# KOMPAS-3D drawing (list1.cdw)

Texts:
  ТОТС.ОПП.00.000.Д1
  График загрузки мастерской. График потребности рабочих по специально- стям. Пространственная организация рабочего места.
  Текст на чертеже
  Размерные надписи
  Шероховатость
  Линия-выноска #1
  Линия-выноска #2
  Линия-выноска #3
  Отклонения формы и база
  Заголовок таблицы
  Ячейка таблицы
  Стрелка вида
  Обозначение изменения
  Фигурная скобка
  Номер узла
  Марка координационной оси
  VRCB
  Выносная надпись
  Обозначение узла
  Марка/позиционное обозначение с линией-выноской
  Марка/позиционное обозначение на линии
  Марка/позиционное обозначение без линии-выноски
  Лист
  Листов
  Рабочее место
  Участок
  Механический
  Пространственная организация
  рабочего места
  (схема)
  Оборудование, оргоснастка, инструмент
  Кол-во
  ГОСТ, ТУ, тип
  модель
  Технологическое
  Станок круглошлифовальный
  Оргоснастка
  Подставка - решетка
  Стол приемный передвижной
  Тумбочка
  Стул подъемно - поворотный
  Урна для мусора
  Техоснастка
  Круг шлифовальный
  Приспособление для правки
  шлифовального круга с кругом
  из карбида кремния ВТ-4Т
  Центр вращающийся
  Морзе №4
  Инструмент
  Ключи гаечные двухсторонние:
  8-10,12-14,17-19,22-24 мм
  ГОСТ 2839-71
  Молоток слесарный
  ПИМ 7215-54
  Напильник плоский личный
  ГОСТ 1465-69
  Напильник полукруглый личный
  Образцы шероховатости
  поверхности
  ГОСТ 9378-60
  Микрометр гладкий
  ГОСТ 6507-60
  Нутромер микрометрический
  ГОСТ 10-58
  Штангенциркуль с двухсто-
  ронним расположением губок
  для наружных и внутренних
  измерений 0-125 мм
  ГОСТ 9378-75
  Инвентарь
  Щетка капроновая
  Документация
  Инструкция по технике безо-
  пасности
  Карта организации труда
  Маршрутный лист
  Технологические карты на
  восстановление и изготов-
  ление деталей
  по 1
  Ящик для хранения мелкой техоснастки
  Ящик для хранения крупной техоснастки
  Ящик для хранения инвентаря
  ГОСТ 2424-67
  Ящик для слесарного и вспомогательного
  инструмента
  Ящик для хранения приспособлений
  Ящик для хранения мерительного инструмента
  Ящик для хранения документации
  ОРГ 9033.000 ЦКТБ
  Россельхозтехника
  ГОСТ 6565-67
  ГОСТ 4785-64
  Обтирочный материал
  Направление
  грузопотока
  янв   фев  март   апр   май  июнь   июль  авг  сент   окт  нояб   дек
  рабочих,
  чел./день
  График потребности рабочих
  по специальностям
  - станочник
  - сварщик
  - медник-жестянщик
  - слесарь
  - кузнец
  -вулканизаторщик
  - досборка и предпродажное техобслуживание
  - ремонт инструмента
  - ТО-1 тракторов
  - ТО-2 тракторов
  - ТО-3 тракторов
  - текущий ремонт тракторов
  - устранение неисправностей тракторов
  - ремонт автотранспорта
  - текущий ремонт сельхозмашин
  - сезонное ТО тракторов
  - ремонт технологического оборудования
  - изготовление и восстановление деталей
  График загрузки мастерской
  дилерского центра
  Напряженность
  работ,
  (чел.-ч.)/день
  - выгрузка
  Ерофеев
  ЧГАУ, кафедра ТОТС
  гр 442
  ТОТС.ОППТС.00.000.Д1-
  График загрузки мастерской. График
  потребности рабочих по специально-
  стям. Пространственная организация
  рабочего места.
Dimensions and other numbers on the sheet: 7; 1.1 Внешняя планировка; 3Б 161; 75-175 мм; 1; 2; 3; 4; 5; 6; 8; 9; 10; 11; 12; 13; 14; 15; 16; 17; 19; 20; 21; 22; 23; 1.2 Схема тумбочки; 18; 25; 30; 35; 40; 45; 50; 55; 60; 65; 70; 75; 80; 85; 90; 95; 280; 240; 200; 160; 120; 480; 440; 400; 360; 320; 600; 520; 560; 640; 680; 720; 760; 800; 840; 880; 920; 960; 1000; 1040; 1080; 0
